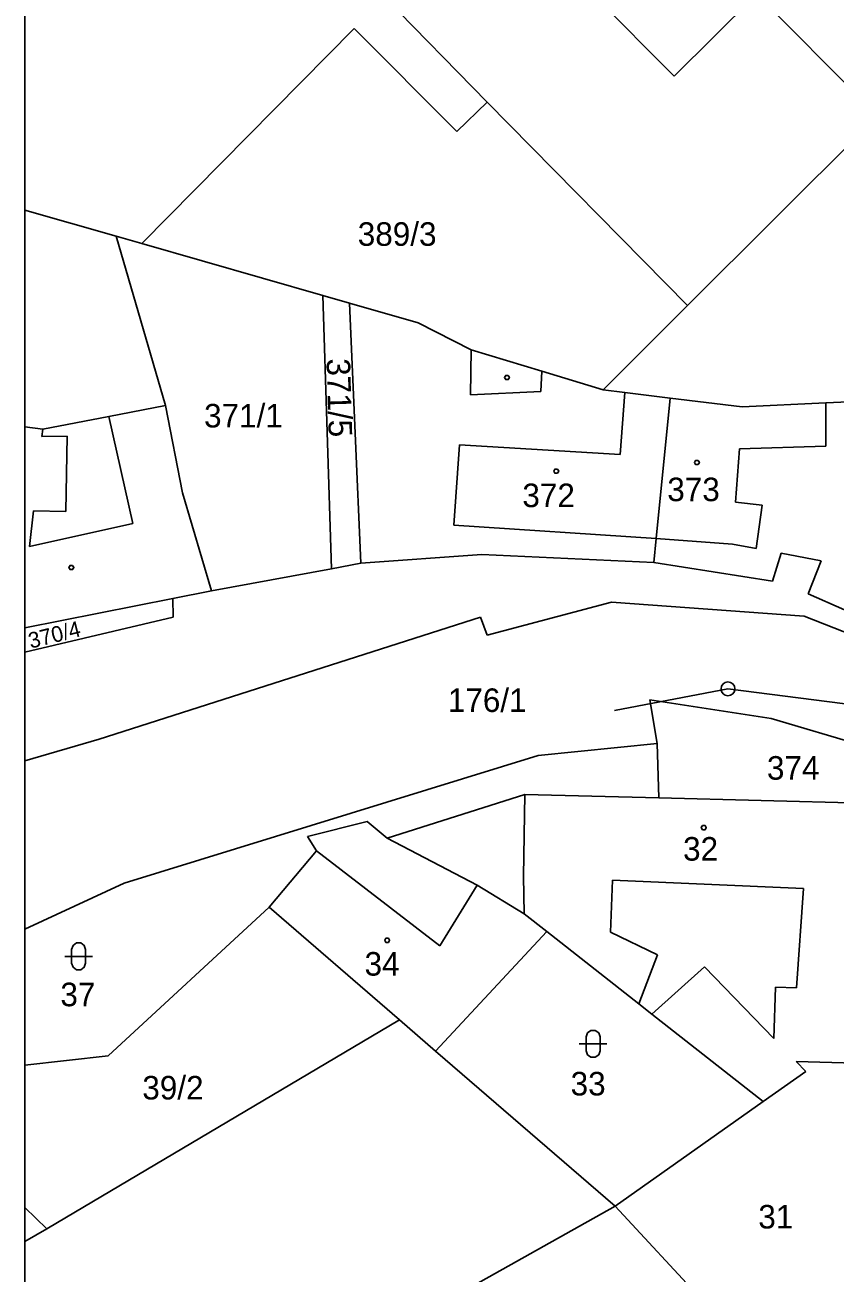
# Model space of a CAD drawing. Extents: x -639621 to -639329, y -1192893 to -1192488.
# Drawn here: x -639621.3 to -639562.8, y -1192743.8 to -1192653.7 of the extents above; entities that cross this region are included whole.
import ezdxf

# ---------------------------------------------------------------- set-up
doc = ezdxf.new("R2010")
doc.units = 0
for name, color, linetype in [('Vrstva 1', 7, 'Continuous'), ('Vrstva 19', 7, 'Continuous'), ('Vrstva 2', 7, 'Continuous'), ('Vrstva 3', 7, 'Continuous'), ('Vrstva 4', 7, 'Continuous'), ('Vrstva 5', 7, 'Continuous'), ('Vrstva 61', 7, 'Continuous')]:
    doc.layers.add(name, color=color, linetype=linetype)

msp = doc.modelspace()

# ---------------------------------------------------------------- linework, layer by layer
at = {"layer": 'Vrstva 1'}
for p, q in [((-639587.88, -1192659.28), (-639597.73, -1192649.2)), ((-639568.41, -1192651.47), (-639559.67, -1192660.27)), ((-639597.48, -1192653.95), (-639612.81, -1192669.48)), ((-639590.06, -1192661.39), (-639597.48, -1192653.95)), ((-639587.88, -1192659.28), (-639590.06, -1192661.39)), ((-639573.4, -1192673.94), (-639587.88, -1192659.28)), ((-639573.4, -1192673.94), (-639559.67, -1192660.27)), ((-639614.68, -1192668.95), (-639621.262, -1192667.062)), ((-639611.11, -1192681.16), (-639614.68, -1192668.95)), ((-639612.81, -1192669.48), (-639614.68, -1192668.95)), ((-639599.75, -1192673.22), (-639612.81, -1192669.48)), ((-639599.75, -1192673.22), (-639599.11, -1192692.94)), ((-639597.81, -1192673.78), (-639599.75, -1192673.22)), ((-639597.81, -1192673.78), (-639597.01, -1192692.55)), ((-639592.87, -1192675.19), (-639597.81, -1192673.78)), ((-639579.49, -1192680.04), (-639573.4, -1192673.94)), ((-639589.03, -1192677.15), (-639592.87, -1192675.19)), ((-639589.03, -1192677.15), (-639583.94, -1192678.69)), ((-639583.94, -1192678.69), (-639579.49, -1192680.04)), ((-639577.94, -1192680.23), (-639579.49, -1192680.04)), ((-639574.65, -1192680.63), (-639577.94, -1192680.23)), ((-639615.21, -1192681.95), (-639611.11, -1192681.16)), ((-639609.89, -1192687.46), (-639611.11, -1192681.16)), ((-639575.67, -1192690.77), (-639574.65, -1192680.63)), ((-639569.45, -1192681.26), (-639574.65, -1192680.63)), ((-639563.42, -1192680.98), (-639569.45, -1192681.26)), ((-639555.06, -1192680.58), (-639563.42, -1192680.98)), ((-639619.98, -1192682.86), (-639615.21, -1192681.95)), ((-639621.262, -1192682.715), (-639619.98, -1192682.86)), ((-639607.78, -1192694.54), (-639609.89, -1192687.46)), ((-639575.67, -1192690.77), (-639575.84, -1192692.5)), ((-639597.01, -1192692.55), (-639588.26, -1192691.91)), ((-639588.26, -1192691.91), (-639575.84, -1192692.5)), ((-639567.27, -1192693.83), (-639566.65, -1192691.83)), ((-639566.65, -1192691.83), (-639563.75, -1192692.37)), ((-639607.78, -1192694.54), (-639599.11, -1192692.94)), ((-639599.11, -1192692.94), (-639597.01, -1192692.55)), ((-639575.84, -1192692.5), (-639567.27, -1192693.83)), ((-639563.75, -1192692.37), (-639564.69, -1192694.76)), ((-639610.58, -1192695.1), (-639607.78, -1192694.54)), ((-639564.69, -1192694.76), (-639562.08, -1192695.91)), ((-639621.262, -1192697.219), (-639610.58, -1192695.1)), ((-639610.58, -1192695.1), (-639610.55, -1192696.43)), ((-639578.89, -1192695.35), (-639587.87, -1192697.73)), ((-639564.99, -1192696.36), (-639578.89, -1192695.35)), ((-639610.55, -1192696.43), (-639621.262, -1192698.969)), ((-639588.35, -1192696.45), (-639615.89, -1192705.25)), ((-639587.87, -1192697.73), (-639588.35, -1192696.45)), ((-639556.03, -1192699.88), (-639564.99, -1192696.36)), ((-639575.61, -1192705.56), (-639576.14, -1192702.41)), ((-639576.14, -1192702.41), (-639567.36, -1192703.76)), ((-639567.36, -1192703.76), (-639555.84, -1192707.16)), ((-639615.89, -1192705.25), (-639621.262, -1192706.807)), ((-639575.61, -1192705.56), (-639584.19, -1192706.43)), ((-639575.61, -1192705.56), (-639575.47, -1192709.49)), ((-639584.19, -1192706.43), (-639614.09, -1192715.64)), ((-639585.15, -1192709.25), (-639595.09, -1192712.38)), ((-639575.47, -1192709.49), (-639585.15, -1192709.25)), ((-639559.39, -1192709.9), (-639575.47, -1192709.49)), ((-639596.55, -1192711.19), (-639600.86, -1192712.26)), ((-639595.09, -1192712.38), (-639596.55, -1192711.19)), ((-639600.86, -1192712.26), (-639600.2, -1192713.3)), ((-639595.09, -1192712.38), (-639588.59, -1192715.79)), ((-639600.2, -1192713.3), (-639603.63, -1192717.36)), ((-639614.09, -1192715.64), (-639621.262, -1192718.967)), ((-639588.59, -1192715.79), (-639585.21, -1192717.84)), ((-639603.63, -1192717.36), (-639615.25, -1192728.1)), ((-639603.63, -1192717.36), (-639594.22, -1192725.5)), ((-639585.21, -1192717.84), (-639583.57, -1192719.13)), ((-639583.57, -1192719.13), (-639591.6, -1192727.76)), ((-639583.57, -1192719.13), (-639576.92, -1192724.35)), ((-639576.92, -1192724.35), (-639575.99, -1192725.08)), ((-639575.99, -1192725.08), (-639567.94, -1192731.4)), ((-639619.69, -1192740.58), (-639594.22, -1192725.5)), ((-639594.22, -1192725.5), (-639591.6, -1192727.76)), ((-639615.25, -1192728.1), (-639621.262, -1192728.784)), ((-639591.6, -1192727.76), (-639578.63, -1192738.96)), ((-639561.27, -1192728.63), (-639565.56, -1192728.52)), ((-639565.56, -1192728.52), (-639564.87, -1192729.23)), ((-639564.87, -1192729.23), (-639567.94, -1192731.4)), ((-639567.94, -1192731.4), (-639578.63, -1192738.96)), ((-639621.262, -1192762.778), (-639578.63, -1192738.96)), ((-639621.262, -1192739.054), (-639619.69, -1192740.58)), ((-639578.63, -1192738.96), (-639567.88, -1192750.5)), ((-639621.262, -1192741.51), (-639619.69, -1192740.58))]:
    msp.add_line(p, q, dxfattribs=at)
at = {"layer": 'Vrstva 19'}
msp.add_lwpolyline([(-639583.962, -1192528.01), (-639550.452, -1192564.184), (-639529.583, -1192588.026), (-639514.491, -1192612.048), (-639507.737, -1192644.326), (-639498.832, -1192694.254), (-639511.439, -1192713.331), (-639516.613, -1192716.507), (-639553.938, -1192703.739), (-639570.485, -1192701.616), (-639578.687, -1192703.18)], dxfattribs=at)
msp.add_circle((-639570.485, -1192701.616), 0.5, dxfattribs=at)
at = {"layer": 'Vrstva 3'}
for points in [[(-639617.89, -1192720.42), (-639617.79, -1192720.13), (-639617.54, -1192719.95), (-639617.23, -1192719.95), (-639616.98, -1192720.13), (-639616.88, -1192720.42), (-639616.88, -1192721.42), (-639616.98, -1192721.71), (-639617.23, -1192721.89), (-639617.54, -1192721.89), (-639617.79, -1192721.71), (-639617.89, -1192721.42)], [(-639580.73, -1192726.73), (-639580.63, -1192726.44), (-639580.38, -1192726.26), (-639580.07, -1192726.26), (-639579.82, -1192726.44), (-639579.72, -1192726.73), (-639579.72, -1192727.73), (-639579.82, -1192728.02), (-639580.07, -1192728.2), (-639580.38, -1192728.2), (-639580.63, -1192728.02), (-639580.73, -1192727.73)]]:
    msp.add_lwpolyline(points, close=True, dxfattribs=at)
for points in [[(-639618.39, -1192720.92), (-639617.12, -1192720.92), (-639616.39, -1192720.92)], [(-639581.23, -1192727.23), (-639579.96, -1192727.23), (-639579.23, -1192727.23)]]:
    msp.add_lwpolyline(points, dxfattribs=at)
at = {"layer": 'Vrstva 4'}
for p, q in [((-639574.37, -1192657.4), (-639601.86, -1192629.73)), ((-639568.41, -1192651.47), (-639574.37, -1192657.4)), ((-639589.03, -1192677.15), (-639589.07, -1192680.4)), ((-639583.99, -1192680.15), (-639583.94, -1192678.69)), ((-639589.07, -1192680.4), (-639583.99, -1192680.15)), ((-639577.94, -1192680.23), (-639578.28, -1192684.7)), ((-639563.42, -1192684.11), (-639563.42, -1192680.98)), ((-639615.21, -1192681.95), (-639613.48, -1192689.67)), ((-639619.98, -1192682.86), (-639620.04, -1192683.4)), ((-639620.04, -1192683.4), (-639618.21, -1192683.38)), ((-639618.21, -1192683.38), (-639618.3, -1192688.81)), ((-639590.28, -1192689.81), (-639589.88, -1192684.01)), ((-639589.88, -1192684.01), (-639578.28, -1192684.7)), ((-639569.93, -1192688.15), (-639569.66, -1192684.29)), ((-639569.66, -1192684.29), (-639563.42, -1192684.11)), ((-639569.93, -1192688.15), (-639568.01, -1192688.35)), ((-639568.01, -1192688.35), (-639568.45, -1192691.49)), ((-639620.64, -1192688.77), (-639620.93, -1192691.34)), ((-639618.3, -1192688.81), (-639620.64, -1192688.77)), ((-639620.93, -1192691.34), (-639613.48, -1192689.67)), ((-639575.67, -1192690.77), (-639590.28, -1192689.81)), ((-639575.67, -1192690.77), (-639570.15, -1192691.17)), ((-639570.15, -1192691.17), (-639568.45, -1192691.49)), ((-639585.15, -1192709.25), (-639585.26, -1192715.14)), ((-639600.2, -1192713.3), (-639591.29, -1192720.15)), ((-639585.26, -1192715.14), (-639585.21, -1192717.84)), ((-639578.98, -1192719.18), (-639578.82, -1192715.42)), ((-639578.82, -1192715.42), (-639565.04, -1192716.02)), ((-639591.29, -1192720.15), (-639588.59, -1192715.79)), ((-639565.04, -1192716.02), (-639565.53, -1192723.19)), ((-639578.98, -1192719.18), (-639575.58, -1192720.81)), ((-639575.58, -1192720.81), (-639576.92, -1192724.35)), ((-639575.99, -1192725.08), (-639572.17, -1192721.67)), ((-639572.17, -1192721.67), (-639567.16, -1192726.86)), ((-639567.05, -1192723.15), (-639567.16, -1192726.86)), ((-639565.53, -1192723.19), (-639567.05, -1192723.15))]:
    msp.add_line(p, q, dxfattribs=at)
at = {"layer": 'Vrstva 5'}
for points in [[(-639586.36, -1192678.99), (-639586.27, -1192679.14), (-639586.36, -1192679.29), (-639586.54, -1192679.29), (-639586.63, -1192679.14), (-639586.54, -1192678.99)], [(-639582.8, -1192685.75), (-639582.71, -1192685.9), (-639582.8, -1192686.05), (-639582.98, -1192686.05), (-639583.07, -1192685.9), (-639582.98, -1192685.75)], [(-639572.64, -1192685.13), (-639572.55, -1192685.28), (-639572.64, -1192685.43), (-639572.82, -1192685.43), (-639572.91, -1192685.28), (-639572.82, -1192685.13)], [(-639617.82, -1192692.7), (-639617.73, -1192692.85), (-639617.82, -1192693), (-639618, -1192693), (-639618.09, -1192692.85), (-639618, -1192692.7)], [(-639572.14, -1192711.48), (-639572.05, -1192711.63), (-639572.14, -1192711.78), (-639572.32, -1192711.78), (-639572.41, -1192711.63), (-639572.32, -1192711.48)], [(-639595.01, -1192719.61), (-639594.92, -1192719.76), (-639595.01, -1192719.91), (-639595.19, -1192719.91), (-639595.28, -1192719.76), (-639595.19, -1192719.61)]]:
    msp.add_lwpolyline(points, close=True, dxfattribs=at)
at = {"layer": 'Vrstva 61'}
msp.add_lwpolyline([(-639621.262, -1192893.333), (-639621.262, -1192487.833)], dxfattribs=at)

# ---------------------------------------------------------------- texts
at = {"layer": 'Vrstva 2'}
for s, p in [('389/3', (-639597.224, -1192669.64)), ('371/1', (-639608.324, -1192682.75)), ('373', (-639574.868, -1192688.07)), ('372', (-639585.335, -1192688.5)), ('176/1', (-639590.718, -1192703.283)), ('374', (-639567.671, -1192708.17)), ('32', (-639573.726, -1192714.01)), ('34', (-639596.732, -1192722.31)), ('37', (-639618.702, -1192724.52)), ('39/2', (-639612.785, -1192731.25)), ('33', (-639581.849, -1192730.96)), ('31', (-639568.294, -1192740.56))]:
    msp.add_text(s, height=1.7, dxfattribs=at).set_placement(p)
for s, height, rotation, p in [('371/5', 1.7, 271.63929, (-639599.481, -1192677.782)), ('370/4', 1.14, 13.98017, (-639620.852, -1192698.718))]:
    msp.add_text(s, height=height, rotation=rotation, dxfattribs=at).set_placement(p)

doc.saveas('drawing.dxf')
